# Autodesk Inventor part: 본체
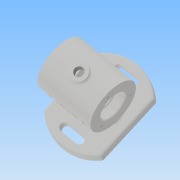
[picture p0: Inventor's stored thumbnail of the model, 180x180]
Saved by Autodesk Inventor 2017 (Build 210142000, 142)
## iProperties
Part Number: 본체
Material: 일반
Document SubType Name: Modeling
Designer: user
Density: 1 g/cm^3
Appearance: 기본값
Author: user
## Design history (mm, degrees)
sketch "스케치1"
  geometry: C1 r 30 at (0, 0); 1 further point
  constraints: 1 centre point, 1 coincident
  dimensions: "d0" = 60 diameter of C1
extrude "돌출1" new body sketch "스케치1" distance "d1" = 70; taper "d2" = 0 deg
node "작업 평면1"
sketch "스케치3"
  geometry: L1 (0, -30)-(70, -30) reference; L2 (35, -30)-(35, 46.791); L3 (0, 0)-(92.901, 0); L4 (72.5, -36.742)-(72.5, 36.742); L5 (-2.5, -36.742)-(-2.5, 36.742); L6 (45, -37)-(25, -37); L7 (45, -42)-(25, -42); L8 (25, -32)-(45, -32); L9 (45, 42)-(25, 42); L10 (25, 32)-(45, 32); A1 r 52.5 centre (35, 0) between (72.5, 36.742) and (-2.5, 36.742); A2 r 52.5 centre (35, 0) between (-2.5, -36.742) and (72.5, -36.742); A3 r 5 centre (45, -37) between (45, -42) and (45, -32); A4 r 5 centre (25, -37) between (25, -32) and (25, -42); A5 r 5 centre (25, 37) between (25, 42) and (25, 32); A6 r 5 centre (45, 37) between (45, 32) and (45, 42); 1 further point
  constraints: 20 end point, 12 point on circle, 6 centre point, 6 symmetric about line, 4 tangent, 3 point on line, 2 midpoint, 2 parallel, 1 horizontal, 1 perpendicular, 1 vertical, 2 other
  dimensions: "d5" = 37.5 distance between parallel lines of L2 L4; "d6" = 52.5 radius of A2; "d7" = 73.48469 distance of L5.start L5.end; "d8" = 52.5 radius of A1; "d10" = 20 distance of L6.start L6.end; "d11" = 5 radius of A3; "d12" = 37 distance of A1.centre point (35, -37); "d13" = 36.74235 vertical distance of A1.centre L5.start
extrude "돌출2" join sketch "스케치3" distance "d14" = 10; taper "d15" = 0 deg
sketch "스케치4"
  geometry: L1 (-45, -32)-(-25, -32) reference; L2 (-25, -42)-(-45, -42) reference; L3 (-25, 32)-(-45, 32) reference; L4 (-45, 42)-(-25, 42) reference; L5 (-72.5, 36.742)-(-72.5, -36.742) reference; L6 (2.5, -36.742)-(2.5, 36.742) reference; A1 r 5 centre (-45, -37) between (-45, -32) and (-45, -42) reference; A2 r 5 centre (-25, -37) between (-25, -42) and (-25, -32) reference; A3 r 5 centre (-25, 37) between (-25, 32) and (-25, 42) reference; A4 r 5 centre (-45, 37) between (-45, 42) and (-45, 32) reference; A5 r 52.5 centre (-35, 0) between (-72.5, -36.742) and (2.5, -36.742) reference; A6 r 52.5 centre (-35, 0) between (2.5, 36.742) and (-72.5, 36.742) reference; 1 further point
sketch "스케치5"
  geometry: L1 (-72.5, 36.742)-(-72.5, -36.742) reference; L2 (2.5, -36.742)-(2.5, 36.742) reference; L3 (2.5, 0)-(-72.5, 0); L4 (-60, 5)-(-10, 5); L5 (-10, 5)-(-10, -5); L6 (-10, -5)-(-60, -5); L7 (-60, -5)-(-60, 5); L8 (-60, 5)-(-10, -5); L9 (-10, 5)-(-60, -5); A1 r 52.5 centre (-35, 0) between (2.5, 36.742) and (-72.5, 36.742) reference; 1 further point
  constraints: 14 end point, 4 midpoint, 2 parallel, 1 horizontal, 1 perpendicular
  dimensions: "d16" = 50 distance of L5.end L6.end; "d17" = 10 distance of L4.end L5.end
extrude "돌출3" join sketch "스케치5" stored distance "d18" = 10; taper "d19" = 0 deg
fillet "모깎기1" dims "d20" = 3
fillet "모깎기2" dims "d21" = 3
fillet "모깎기3" dims "d22" = 3
fillet "모깎기4" dims "d23" = 3
node "작업 평면2"
sketch "스케치6"
  geometry: C1 r 10 at (35, 0); 2 further points
  constraints: 1 centre point, 1 coincident, 1 horizontal alignment
  dimensions: "d25" = 35 distance of point (0, 0) point (35, 0); "d26" = 20 diameter of C1
extrude "돌출4" join sketch "스케치6" stored distance "d27" = 10; taper "d28" = 0 deg
sketch "스케치7"
  geometry: C1 r 10 at (0, 0) reference; 1 further point
hole "구멍1" sketch "스케치7" at (0, 0) diameter "d29" = 10.917; stored, may be unused: countersink angle "d33" = 90 deg, drill point angle "d35" = 118 deg; dims "d30" = 24, "d31" = 4, "d32" = 2, "d34" = 29.1
fillet "모깎기5" dims "d36" = 3
sketch "스케치9"
  geometry: C1 r 30 at (0, 0) reference; C2 r 16 at (0, 0)
  constraints: 1 centre point, 1 coincident
  dimensions: "d37" = 32 diameter of C2
extrude "돌출5" cut sketch "스케치9" distance "d38" = 12; taper "d39" = 0 deg
sketch "스케치10"
  geometry: C1 r 16 at (0, 0) reference; C2 r 14 at (0, 0)
  constraints: 1 centre point, 1 coincident
  dimensions: "d40" = 28 diameter of C2
extrude "돌출6" cut sketch "스케치10" distance "d41" = 3; taper "d42" = 0 deg
sketch "스케치11"
  geometry: C1 r 14 at (0, 0) reference; C2 r 25 at (0, 0)
  constraints: 1 centre point, 1 coincident
  dimensions: "d43" = 50 diameter of C2
extrude "돌출7" cut sketch "스케치11" distance "d44" = 40; taper "d45" = 0 deg
sketch "스케치12"
  geometry: C1 r 25 at (0, 0) reference; C2 r 14 at (0, 0)
  constraints: 1 centre point, 1 coincident
  dimensions: "d46" = 28 diameter of C2
extrude "돌출8" cut sketch "스케치12" distance "d47" = 3; taper "d48" = 0 deg
sketch "스케치13"
  geometry: C1 r 14 at (0, 0) reference; C2 r 16 at (0, 0)
  constraints: 1 centre point, 1 coincident
  dimensions: "d49" = 32 diameter of C2
extrude "돌출9" cut sketch "스케치13" distance "d50" = 12; taper "d51" = 0 deg
chamfer "모따기1" distance "d52" = 1; stored, may be unused: second distance "d53" = 2, angle "d54" = 45 deg
fillet "모깎기6" dims "d55" = 3
fillet "모깎기7" dims "d56" = 0.3
fillet "모깎기8" dims "d57" = 0.3
sketch "스케치14" dims "d58" = 46
  geometry: C1 r 17 at (0, 0) reference; 2 further points
  constraints: 1 coincident, 1 vertical alignment, 2 other
hole "구멍2" sketch "스케치14" at (0, 23) diameter "d59" = 3.242; stored, may be unused: countersink angle "d63" = 90 deg, drill point angle "d65" = 118 deg; dims "d60" = 8, "d61" = 4, "d62" = 2, "d64" = 10
node "작업 평면3"
node "작업 평면4"
sketch "스케치15"
  geometry: L1 (0, 30)-(-70, 30) reference; L2 (-70, 30)-(-70, -30) reference; 2 further points
  constraints: 1 other
  dimensions: "d70" = 30 distance from line of L1 point (-35, 0); "d71" = 35 distance from line of L2 point (-35, 0)
feature "엠보싱1" sketch "스케치15" dims "d72" = 0.5, "d73" = 0
node "솔리드1"
pattern_circular "원형 패턴1" dims angle "d67" = 360 deg
mirror "미러1"
other parameters: "d3" = -62, "d4" = 105, "d24" = 33, "d69" = 54.25
